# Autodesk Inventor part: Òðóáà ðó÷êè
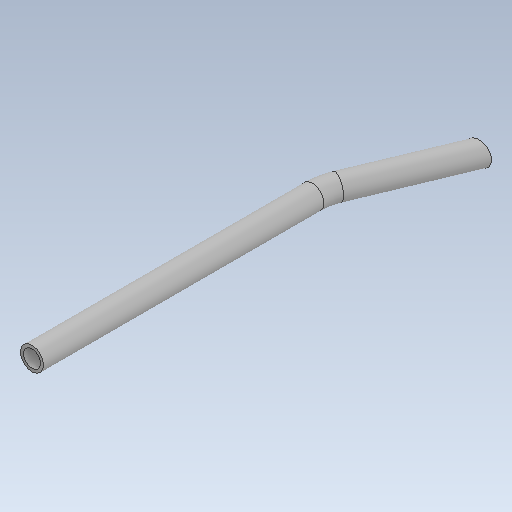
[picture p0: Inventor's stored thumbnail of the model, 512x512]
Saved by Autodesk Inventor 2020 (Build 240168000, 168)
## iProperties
Created: 1900-01
Part Number: Òðóáà ðó÷êè
Material: Générique
Document SubType Name: Modeling
Designer: bruno
Density: 1 g/cm^3
Appearance: Par défaut
Author: bruno
Revision Number: ANYUNSPECIFIED
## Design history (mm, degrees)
feature "Base1"
node "Solide1"
